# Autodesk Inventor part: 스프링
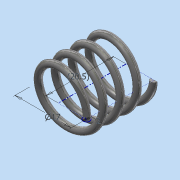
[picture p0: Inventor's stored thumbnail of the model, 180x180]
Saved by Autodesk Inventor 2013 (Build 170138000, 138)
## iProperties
Created: 2017-07
Part Number: 스프링
Material: 스테인리스강
Document SubType Name: Modeling
Designer: dgall
Mass: 5.31911 g
Surface Area: 13.384 cm^2
Volume: 0.658305 cm^3
Density: 8.08 g/cm^3
Author: dgall
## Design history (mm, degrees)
sketch "스케치1"
  geometry: L1 (0, 0)-(8.5, 0); L2 (8.5, 0)-(8.5, 20.5); L3 (8.5, 20.5)-(0, 20.5); L4 (0, 20.5)-(0, 0); C1 r 1 at (8.5, 0)
  constraints: 8 end point, 2 parallel, 1 centre point, 1 coincident, 1 horizontal, 1 perpendicular
  dimensions: "d0" = 2 diameter of C1; "d1" = 17 diameter of L2 L4; "d2" = 20.5 distance of L3.end L1.start (derived)
feature "코일1" pitch "d3" = 2 (= d0); turns "d5" = 4; dims "d4" = 20.5 (= d2), "d6" = 0, angle "d7" = 90 deg, angle "d8" = 90 deg, "d9" = 0, "d10" = 0
node "작업 평면2"
  node "작업 평면1"
feature "분할1"
feature "분할2"
node "솔리드1"
other parameters: "d11" = 0, "d12" = 0
